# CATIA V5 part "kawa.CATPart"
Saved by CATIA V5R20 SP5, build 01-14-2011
Part number: 卡瓦
Bounding box of the stored display mesh (mm): x -43.58 to 74, y -43.996 to 9.935, z 0 to 70
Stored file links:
  E:\画图\kawa.CATPart
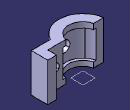
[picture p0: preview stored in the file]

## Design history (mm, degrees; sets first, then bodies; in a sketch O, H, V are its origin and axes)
Body1 (main body)
  Sketch1 on xy-plane, origin (0, 0, 0), H (1, 0, 0), V (0, 1, 0)
    arc A1 centre (0, 0) radius 26 from (-25.2827, -6.0652) to (25.2827, -6.0652) ccw
    arc A2 centre (0, 0) radius 44 from (-43.58, -6.0652) to (39.1585, -20.0652) ccw
    line L1 (-43.58, -6.0652) -> (-25.2827, -6.0652)
    line L2 (58, 9.9348) -> (58, -6.0652)
    line L3 (58, 9.9348) -> (74, 9.9348)
    line L4 (74, 9.9348) -> (74, -20.0652)
    line L5 (39.1585, -20.0652) -> (74, -20.0652)
    point P8 (25.2827, -6.0652)
    line L6 (25.2827, -6.0652) -> (58, -6.0652)
    radius A1 = 26
    radius A2 = 44
    length L4 = 30
    length L2 = 16
    distance V L4 = 74
    length L3 = 16
    horizontal: L1 H, L3 H, L5 H, L6 H
    vertical: L2 V, L4 V
    coincidence: L1 P8, L1 L6
  Pad1: profile Sketch1, direction (0, 0, 1), length 70
  Sketch2 on face of Pad1 from Sketch1.L1, origin (0, -6.0652, 0), H (-1, 0, 0), V (0, 0, 1)
    line L1 (19.5653, 60.1494) -> (30.2951, 60.1494)
    line L2 (30.2951, 60.1494) -> (30.2951, 9.4794)
    line L3 (30.2951, 9.4794) -> (19.5653, 9.4794)
    line L4 (19.5653, 9.4794) -> (19.5653, 60.1494)
    horizontal: L1 H, L3 H
    vertical: L2 V, L4 V
  Groove1: profile Sketch2, axis axis of face of Pad1 from Sketch1.A1, angle 360
  Sketch3 on {plane type Tangent, Support face of Groove1 from Sketch2.L2, RefPoint {point type OnSurface, Support face of Groove1 from Sketch2.L2, RefPoint {point stored without definition}, Length 0, Direction (0, 0, -1000)}}, origin (3.9441, -30.6434, 32.6412), H (0.9918, 0.1277, 0), V (0, 0, -1)
    point P1 (-0.6454, -2.6345)
  Hole1: placed by Sketch3, at (3.3032, -30.7191, 35.2757) direction (0.1069, -0.9943, 0), diameter 20, through (limit type 3)
  Sketch4 on face of Pad1 from Sketch1.L6, origin (45.0993, -6.0652, 33.0082), H (1, 0, 0), V (0, 0, -1)
    point P1 (-0.0039, -1.5252)
  Hole2: placed by Sketch4, at (45.0954, -6.0652, 34.5334) direction (0, -1, 0), diameter 16, depth 7.649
